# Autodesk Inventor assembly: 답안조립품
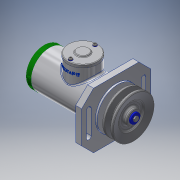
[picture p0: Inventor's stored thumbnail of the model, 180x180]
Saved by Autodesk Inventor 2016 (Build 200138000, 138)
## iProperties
Created: 2017-10
Part Number: 답안조립품
Material: 일반
Document SubType Name: Assembly
Designer: USER
Author: USER
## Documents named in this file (20)
- C:\Users\USER\Desktop\471007V1019\답안조립품.iam
- C:\Users\USER\Desktop\471007V1019\본체.ipt
- C:\Users\USER\Desktop\471007V1019\V-벨트풀리.ipt
- C:\Users\USER\Desktop\471007V1019\너트 M10.ipt
- C:\Users\USER\Desktop\471007V1019\멈춤링 15 x 1.ipt
- C:\Users\USER\Desktop\471007V1019\멈춤링 35x1.6.ipt
- C:\Users\USER\Desktop\471007V1019\베어링 15 x 35 x 11.ipt
- C:\Users\USER\Desktop\471007V1019\볼트 M4 x 10.ipt
- C:\Users\USER\Desktop\471007V1019\부시1.ipt
- C:\Users\USER\Desktop\471007V1019\부시2.ipt
- C:\Users\USER\Desktop\471007V1019\사이드 커버.ipt
- 사이드 커버.ipt
- C:\Users\USER\Desktop\471007V1019\십자볼트 M3 x 10.ipt
- C:\Users\USER\Desktop\471007V1019\오일 실 15 25 7.ipt
- C:\Users\USER\Desktop\471007V1019\와셔 3x6.ipt
- C:\Users\USER\Desktop\471007V1019\와셔 4x16.ipt
- C:\Users\USER\Desktop\471007V1019\와셔 10x21.ipt
- C:\Users\USER\Desktop\471007V1019\축.ipt
- C:\Users\USER\Desktop\471007V1019\키 4 x 4 x 18.ipt
- C:\Users\USER\Desktop\471007V1019\탑 커버.ipt
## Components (2 placed, 2 different names)
1. V-벨트풀리:1
2. ISO 4017 M4 x 10:1
